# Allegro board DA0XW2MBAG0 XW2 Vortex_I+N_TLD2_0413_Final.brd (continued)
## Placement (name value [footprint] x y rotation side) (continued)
C3637  1u/25V_6  [C0603]  348.29 23.99 270 top
C3638  2.2U/10V_4  [C0402]  356.14 23.71 180 top
C3639  100p/50V_4  [C0402]  356.24 11.42 180 top
C3640  100p/50V_4  [C0402]  354.49 3.39 270 top
C3641  100p/50V_4  [C0402]  356.39 7.2 0 top
C3642  0.1u/16V_4  [C0402]  356.39 25.24 270 top
C3643  0.1u/16V_4  [C0402]  353.42 10.07 180 top
C3644  0.1u/16V_4  [C0402]  355.51 16.09 180 top
C3645  0.1U/16V_2  [C0201]  196.53 158.54 180 top
C3646  0.1U/16V_2  [C0201]  223.04 157.32 270 top
C3647  10u/6.3V_6  [C0603]  195.87 158.55 0 bottom
C3648  0.1u/16V_4  [C0402]  195.87 156.27 180 bottom
C3649  0.1u/16V_4  [C0402]  195.87 157.28 180 bottom
C3650  10u/6.3V_6  [C0603]  227.62 153.23 90 bottom
C3651  0.1u/16V_4  [C0402]  225.84 156.94 270 top
C3652  0.1u/16V_4  [C0402]  226.84 156.95 270 top
C3653  10u/25V_6  [C0603]  203.74 154.11 180 bottom
C3654  10u/25V_6  [C0603]  203.74 155.63 180 bottom
C3655  10u/25V_6  [C0603]  203.74 157.16 180 bottom
C3656  10u/25V_6  [C0603]  203.74 158.68 180 bottom
C3657  10u/25V_6  [C0603]  223.04 153.22 90 bottom
C3658  10u/25V_6  [C0603]  224.57 153.22 90 bottom
C3659  10u/25V_6  [C0603]  226.09 153.22 90 bottom
C3660  10u/25V_6  [C0603]  221.52 153.22 90 bottom
C3661  47p/50V_4  [C0402]  214.54 153.47 90 top
C3662  47p/50V_4  [C0402]  213.52 153.47 90 top
C3663  47p/50V_4  [C0402]  212.5 153.47 90 top
C3664  47p/50V_4  [C0402]  211.49 153.47 90 top
C3665  47p/50V_4  [C0402]  206.03 156.55 270 top
C3666  47p/50V_4  [C0402]  218.09 155.41 90 top
C3667  47p/50V_4  [C0402]  218.09 152.62 90 top
C3668  47p/50V_4  [C0402]  205.77 153.63 90 top
C3669  *10u/25V_6  [C0603]  330.87 10.92 270 top
C3670  *10u/25V_6  [C0603]  329.44 10.92 270 top
C4000  0.1U/16V_4  [C0402]  28.1 118.07 270 bottom
C4001  0.1U/16V_4  [C0402]  27.08 118.07 270 bottom
C4002  22U/6.3V_6  [C0603]  31.02 125.95 270 bottom
C4003  0.1U/16V_4  [C0402]  23.27 124.04 180 top
C4004  1U/10V_4  [C0402]  26.07 126.96 90 top
C4005  0.1U/16V_4  [C0402]  23.15 126.07 180 top
C4006  10u/6.3V_6  [C0603]  24.8 126.96 270 top
C4007  10u/6.3V_6  [C0603]  23.78 117.31 270 bottom
C4008  10P/50V_4  [C0402]  19.08 128.23 180 bottom
C4009  12p/50V_4  [C0402]  20.86 128.23 0 bottom
C4010  1U/6.3V_4  [C0402]  26.96 138.39 0 bottom
C4011  0.01U/100V_6  [C0603]  23.15 137.25 180 bottom
C4012  0.1U/16V_4  [C0402]  26.96 142.46 0 bottom
C4013  0.01U/100V_6  [C0603]  23.15 138.77 180 bottom
C4014  0.1U/16V_4  [C0402]  26.96 143.47 0 bottom
C4015  0.01U/100V_6  [C0603]  23.15 143.73 180 bottom
C4016  0.1U/16V_4  [C0402]  26.96 144.49 0 bottom
C4017  0.01U/100V_6  [C0603]  23.15 145.25 180 bottom
C4018  0.1U/16V_4  [C0402]  26.96 137.38 0 bottom
C4019  10P/3KV_1808  [CC1808]  24.54 134.96 180 bottom
C4100  1u/6.3V_4  [C0402]  326.04 74.64 90 bottom
C4101  0.1u/16V_4  [C0402]  329.85 79.59 270 bottom
C4102  0.1u/16V_4  [C0402]  328.84 79.59 270 bottom
C4103  4.7u/6.3V_4  [C0402_2]  331.63 79.72 0 bottom
C4104  0.1u/16V_4  [C0402]  333.66 78.45 270 bottom
C4105  3.3P/50V_4  [C0402]  335.69 78.45 90 bottom
C4106  10u/6.3V/X5R_4  [C0402]  334.68 78.45 90 bottom
C4107  10u/6.3V/X5R_4  [C0402]  334.75 59.86 180 bottom
C4108  0.01U/50V_4  [C0402]  336.71 77.05 90 bottom
C4109  0.1u/16V_4  [C0402]  333.03 61.3 90 bottom
C4110  0.01U/50V_4  [C0402]  334.02 61.3 270 bottom
C4111  *0_4/S  [S0402]  350.3 69.31 0 bottom
C4112  *0_4/S  [S0402]  350.3 68.29 0 bottom
C4200  470p/50V_4  [C0402]  304.32 12.92 90 top
C4201  3.3P/50V_4  [C0402]  331.78 21.46 0 bottom
C4202  10U/6.3V_4  [C0402]  331.78 19.3 180 bottom
C4203  *0.1u/16V_4  [C0402]  341.03 19.3 90 bottom
C4204  4.7u/6.3V_4  [C0402_2]  311.63 10.09 180 top
C4205  1u/6.3V_4  [C0402]  344.05 21.91 180 bottom
C4206  56p/50V_4  [C0402]  342.89 28.15 270 top
C4207  18p/50V_4  [C0402]  307.37 12.92 90 top
C4208  56p/50V_4  [C0402]  341.87 28.16 270 top
C4209  0.1u/16V_4  [C0402]  346.77 19.06 0 bottom
C4210  18p/50V_4  [C0402]  309.66 12.92 90 top
C4211  18p/50V_4  [C0402]  311.63 11.23 0 top
C4212  220u/6.3V_3528H1.9  [C3528]  340.01 25.54 0 top
C4213  68P/50V_4  [C0402]  346.77 18.06 180 bottom
C4214  18p/50V_4  [C0402]  308.39 12.92 90 top
C4215  33p/50V_4  [C0402]  345.68 5.94 90 bottom
C4216  0.1u/16V_4  [C0402]  311.63 12.25 180 top
C4217  10U/6.3V_4  [C0402]  349.74 18.07 0 bottom
C4218  56p/50V_4  [C0402]  344.99 20.54 90 bottom
C4219  *220u/6.3V_3528H1.9  [C3528]  330.69 26.3 270 top
C4220  *6.8P/50V_4  [C0402]  331.78 20.44 180 bottom
C4221  33p/50V_4  [C0402]  328.58 20.82 0 bottom
C4222  47p/50V_4  [C0402]  328.58 19.81 0 bottom
C4223  56p/50V_4  [C0402]  328.58 18.79 180 bottom
C4224  68P/50V_4  [C0402]  328.58 17.78 180 bottom
C4225  *22u/6.3V_6  [C0603]  329.85 18.12 180 top
C4226  *47u/6.3V_8  [C0805]  329.98 16.35 180 top
C5001  0.1u/16V_4  [C0402]  39.78 47.21 90 bottom
C5002  10u/6.3V_6  [C0603]  41.18 47.21 90 bottom
C5003  10U/10V/X5R_8  [C0805]  42.96 47.46 270 bottom
C5100  68p/50V_4  [C0402]  318.29 12.28 0 top
C5101  0.1u/16V_4  [C0402]  318.75 5.17 0 top
C5102  1000P/50V_4  [C0402]  318.29 9.23 0 top
C5103  3.3p/50V_4  [C0402]  309.02 26 180 bottom
C5104  1000P/50V_4  [C0402]  318.29 10.25 0 top
C5105  3.3p/50V_4  [C0402]  318.29 11.27 0 top
C5106  1000P/50V_4  [C0402]  309.02 28.03 180 bottom
C5107  0.1u/16V_4  [C0402]  313.09 31.97 90 bottom
C5112  0.1u/16V_4  [C0402]  309.02 27.01 180 bottom
C5113  1000P/50V_4  [C0402]  312.73 44.69 90 bottom
C5114  68p/50V_4  [C0402]  309.02 24.98 180 bottom
C5115  0.1u/16V_4  [C0402]  311.31 19.9 180 bottom
C5121  *22u/6.3V_6  [C0603]  308.98 34.18 0 bottom
C5122  *47u/6.3V_8  [C0805]  309.22 32.44 0 bottom
C6001  10U/6.3V_4  [C0402]  276 28.03 180 top
C6002  0.1u/6.3V_2  [C0201]  274.73 27.9 90 top
C6003  10U/6.3V_4  [C0402]  260.08 28.67 270 bottom
C6004  1U/10V_2  [C0201]  266.54 33.57 270 top
C6006  0.1u/6.3V_2  [C0201]  262.29 27.6 180 bottom
C6007  1U/10V_2  [C0201]  268.38 20.66 90 bottom
C6008  2200P/50V_4  [C0402]  262.13 26.25 270 bottom
C6009  2200P/50V_4  [C0402]  261.17 26.25 270 bottom
C6011  2200P/50V_4  [C0402]  260.2 26.25 90 bottom
C6012  10U/6.3V_4  [C0402]  270.03 34.76 0 bottom
C6015  0.1u/6.3V_2  [C0201]  264.32 24.35 180 top
C6016  0.1u/6.3V_2  [C0201]  270.03 33.75 0 bottom
C6017  4.7u/6.3V_4  [C0402]  260.64 25.24 270 top
C6018  0.1u/6.3V_2  [C0201]  261.53 25.62 270 top
C6019  1U/10V_2  [C0201]  261.65 26.76 0 top
C6020  VARISTOR  [C0402]  35.47 141.7 90 bottom
C6022  VARISTOR  [C0402]  30.89 141.57 0 bottom
C6029  0.1u/16V_4  [C0402]  263.81 13.17 0 top
C6030  0.1u/6.3V_2  [C0201]  269.15 22.44 270 top
C6031  0.1u/6.3V_2  [C0201]  274.35 25.74 90 top
C6032  0.1u/6.3V_2  [C0201]  266.86 34.13 270 bottom
C6033  *0.1u/6.3V_2  [C0201]  251.11 50.38 270 top
C6038  2200P/50V_4  [C0402]  258.78 22.62 180 top
C6039  2200P/50V_4  [C0402]  258.86 24.6 270 top
C6201  0.1u/16V_4  [C0402]  316.26 49.75 90 bottom
C6202  0.1u/16V_4  [C0402]  299.75 59.27 270 bottom
C6203  1u/10V_4  [C0402]  302.22 57.19 270 bottom
C6204  *0.1u/16V_4  [C0402]  298.74 59.27 270 bottom
C6300  *10p/50V_4  [C0402]  336.68 87.9 270 bottom
C6301  *VARISTOR  [C0402]  26.83 94.71 90 bottom
C6302  10u/6.3V_6  [C0603]  25.31 97.12 90 bottom
C6303  *10p/50V_4  [C0402]  25.81 94.71 270 bottom
C6304  0.1u/16V_4  [C0402]  26.58 97.12 270 bottom
C6305  47p/50V_4  [C0402]  25.18 100.04 0 bottom
C6306  10u/6.3V_6  [C0603]  319.69 72.35 0 bottom
C6307  0.1u/16V_4  [C0402]  319.69 73.62 180 bottom
C6308  *VARISTOR  [C0402]  335.69 87.9 90 bottom
C6309  47p/50V_4  [C0402]  323.37 72.73 180 bottom
C6351  *10p/50V_4  [C0402]  101.63 3.34 90 top
C6352  12p/50V_4  [C0402]  104.93 3.34 90 top
C6353  0.1u/16V_4  [C0402]  105.44 5.93 90 top
C6354  12p/50V_4  [C0402]  102.9 3.34 90 top
C6355  *10p/50V_4  [C0402]  100.62 3.34 90 top
C6401  0.01U/50V_4  [C0402]  170.09 88.18 0 bottom
C6402  2200P/50V_4  [C0402]  188.75 47.59 90 top
C6403  0.1u/16V_4  [C0402]  121.44 112.2 0 top
C6500  0.1u/16V_4  [C0402]  294.29 56.73 90 top
C6501  0.1u/16V_4  [C0402]  299.37 56.61 90 top
C6502  0.1u/16V_4  [C0402]  307.5 45.61 270 bottom
C6503  0.1u/16V_4  [C0402]  305.09 41.49 270 bottom
C6504  1u/6.3V_4  [C0402]  291.75 50.38 270 top
C6800  0.1u/16V_4  [C0402]  238.03 50.89 180 bottom
C6801  *VARISTOR  [C0402]  233.97 41.87 0 bottom
C6802  *VARISTOR  [C0402]  232.57 36.74 270 bottom
C6803  *VARISTOR  [C0402]  230.92 42.89 180 bottom
C6804  *VARISTOR  [C0402]  230.92 46.95 180 bottom
C6805  *VARISTOR  [C0402]  233.97 42.89 0 bottom
C6806  *VARISTOR  [C0402]  233.97 38.83 0 bottom
C6807  *VARISTOR  [C0402]  233.97 43.91 0 bottom
C6808  *VARISTOR  [C0402]  230.92 43.91 180 bottom
C6809  *VARISTOR  [C0402]  230.92 41.87 180 bottom
C6810  *VARISTOR  [C0402]  230.92 44.92 180 bottom
C6811  *VARISTOR  [C0402]  233.97 47.97 0 bottom
C6812  *VARISTOR  [C0402]  231.55 36.74 270 bottom
C6813  *VARISTOR  [C0402]  230.92 47.97 180 bottom
C6814  *VARISTOR  [C0402]  230.92 45.94 180 bottom
C6815  *VARISTOR  [C0402]  233.97 48.99 0 bottom
C6816  *VARISTOR  [C0402]  233.97 45.94 0 bottom
C6817  *VARISTOR  [C0402]  230.92 39.84 180 bottom
C6818  *VARISTOR  [C0402]  233.97 44.92 0 bottom
C6819  *VARISTOR  [C0402]  230.92 50 180 bottom
C6820  *VARISTOR  [C0402]  233.97 51.02 0 bottom
C6821  *VARISTOR  [C0402]  230.92 40.86 180 bottom
C6822  *VARISTOR  [C0402]  233.97 46.95 0 bottom
C6823  *VARISTOR  [C0402]  233.97 50 0 bottom
C6824  *VARISTOR  [C0402]  233.97 37.81 0 bottom
C6825  1u/10V_4  [C0402]  196.12 45.94 0 top
C6826  *VARISTOR  [C0402]  233.97 40.86 0 bottom
C6827  *VARISTOR  [C0402]  230.92 48.99 180 bottom
C6828  *VARISTOR  [C0402]  233.97 39.84 0 bottom
C6829  *VARISTOR  [C0402]  244.89 53.68 180 top
C6830  *VARISTOR  [C0402]  231.05 51.02 180 bottom
C6831  *VARISTOR  [C0402]  233.97 52.03 0 bottom
C7000  470p/50V_4  [C0402]  349.79 78.45 270 top
C7001  0.1u/16V_4  [C0402]  18.27 105.73 270 top
C7002  470p/50V_4  [C0402]  19.29 105.73 270 top
C7003  0.1u/16V_4  [C0402]  16.95 95.11 270 top
C7004  470p/50V_4  [C0402]  15.93 95.11 270 top
C7005  1000P/50V_4  [C0402]  17.25 105.73 90 top
C7006  1000P/50V_4  [C0402]  17.96 95.11 90 top
C7007  0.1u/16V_4  [C0402]  354.62 78.45 90 top
C7008  470p/50V_4  [C0402]  350.81 78.45 90 top
C7009  1000P/50V_4  [C0402]  352.61 78.45 270 top
C7010  PESD5V0X2UM  [DFN1006H4-3-1X0_6-3P]  16.16 108.8 270 top
C7011  PESD5V0X2UM  [DFN1006H4-3-1X0_6-3P]  15.91 87.34 270 top
C7012  PESD5V0X2UM  [DFN1006H4-3-1X0_6-3P]  355.38 77.05 90 bottom
C7013  4.7u/6.3V_4  [C0402_2]  353.22 88.74 0 top
C7014  4.7u/6.3V_4  [C0402_2]  17.89 96.76 180 top
C7015  4.7u/6.3V_4  [C0402_2]  22.18 96.05 0 top
C7016  0.1u/16V_4  [C0402]  353.22 86.7 0 top
C7017  0.1u/16V_4  [C0402]  17.89 97.91 180 top
C7018  0.1u/16V_4  [C0402]  22.18 94.91 0 top
C7019  100u/6.3V_3528H1.9  [C3528]  349.79 83.02 270 top
C7020  470p/50V_4  [C0402]  18.96 95.11 90 top
C7021  100u/6.3V_3528H1.9  [C3528]  16.24 101.54 90 top
C7022  470p/50V_4  [C0402]  20.35 101.94 270 top
C7023  100u/6.3V_3528H1.9  [C3528]  16.92 90.85 0 top
C7100  0.47U/25V_4  [C0402]  361.6 113.76 270 bottom
C7102  0.47U/25V_4  [C0402]  363.66 133.85 90 bottom
C7103  10u/25V_8  [C0805]  364.47 129.88 270 bottom
C7104  0.47U/25V_4  [C0402]  361.8 132.81 270 bottom
C7105  0.47U/25V_4  [C0402]  361.6 130.39 270 bottom
C7107  10u/25V_8  [C0805]  364.47 113.25 270 bottom
C7108  0.47U/25V_4  [C0402]  363.84 117.16 90 bottom
C7109  0.47U/25V_4  [C0402]  361.83 116.12 270 bottom
C7110  0.47U/25V_4  [C0402]  364.65 134.71 90 bottom
C7111  0.47U/25V_4  [C0402]  364.8 118.12 90 bottom
C7138  47u/10V_8  [C0805]  352.71 137.63 180 top
C7139  *47u/10V_8  [C0805]  351.95 135.6 180 top
C7140  10U/6.3V_4  [C0402]  348.77 139.16 270 top
C7141  0.1u/16V_4  [C0402]  349.76 139.16 270 top
C7146  10U/6.3V_4  [C0402]  350.68 134.08 180 top
C7147  0.1u/16V_4  [C0402]  350.68 133.11 180 top
C7152  0.001u/50V_4  [C0402]  354.46 143.27 0 top
C7153  0.001u/50V_4  [C0402]  342.55 132.3 180 top
C7154  *47u/10V_8  [C0805]  348.14 137.17 0 top
C7155  47u/10V_8  [C0805]  348.14 135.19 0 top
C7200  0.1u/16V_4  [C0402]  289.21 10.25 0 top
C7201  4.7u/6.3V_4  [C0402_2]  289.21 9.11 0 top
C7300  0.1U/16V_4  [C0402]  286.29 14.31 0 top
C7301  1U/10V_4  [C0402]  283.14 8.93 90 top
C7302  82P/50V_4  [C0402]  284.21 8.93 90 top
C7303  1U/10V_4  [C0402]  284.26 20.77 270 bottom
C7304  0.1U/16V_4  [C0402]  282.2 14.37 270 top
C7305  1U/10V_4  [C0402]  282.07 8.93 90 top
C7306  0.1U/16V_4  [C0402]  281.85 20.77 270 bottom
C7307  1U/10V_4  [C0402]  279.66 11.52 90 top
C7308  0.1U/16V_4  [C0402]  280.7 11.52 90 top
C7309  0.1U/16V_4  [C0402]  280.83 20.77 270 bottom
C7310  1U/10V_4  [C0402]  279.81 20.77 270 bottom
C7311  *47P/50V_4  [C0402]  277.53 9.11 270 top
C7312  1U/10V_4  [C0402]  280.17 14.37 270 top
C7313  0.1U/16V_4  [C0402]  279.15 14.37 270 top
C7314  *12pF_4  [C0402]  288.96 20.36 180 bottom
C7315  *12pF_4  [C0402]  287.05 20.36 0 bottom
C7316  0.1u/16V_4  [C0402]  28.71 75.17 270 bottom
C7317  10U/6.3VS_6  [C0603]  27.46 75.27 90 bottom
C7318  1u/10V_4  [C0402]  25.56 74.39 270 bottom
C7319  0.1u/16V_4  [C0402]  34.27 67.2 0 bottom
C7320  1u/10V_4  [C0402]  24.52 67.58 0 bottom
C7321  0.1u/16V_4  [C0402]  34.27 68.21 0 bottom
C7322  *100p/50V_4  [C0402]  33.51 66.18 0 bottom
C7323  0.1u/16V_4  [C0402]  27.69 64.4 90 bottom
C7324  0.1u/16V_4  [C0402]  32.09 65.29 270 bottom
C7325  4.7U/6.3VS_4  [C0402]  26.68 64.4 270 bottom
C7326  10u/6.3V_6  [C0603]  31.12 63.64 0 bottom
C7327  0.1u/16V_4  [C0402]  30.69 64.91 180 bottom
C7328  0.1u/16V_4  [C0402]  36.23 63.08 270 top
C7329  4.7U/6.3V_6  [C0603]  36.35 60.8 270 top
C7330  0.1u/16V_4  [C0402]  34.58 63.79 270 bottom
C7331  *0.1u/16V_4  [C0402]  38.54 65.04 180 bottom
C7332  4.7U/6.3V_6  [C0603]  36.61 67.02 90 bottom
C8000  0.22uF/6.3V_2  [C0201]  337.22 107.53 180 bottom
C8001  0.22uF/6.3V_2  [C0201]  337.22 108.29 180 bottom
C8002  0.22uF/6.3V_2  [C0201]  337.22 110.58 180 bottom
C8003  0.22uF/6.3V_2  [C0201]  337.22 111.34 180 bottom
C8004  0.22uF/6.3V_2  [C0201]  337.22 114.39 180 bottom
C8005  0.22uF/6.3V_2  [C0201]  337.22 113.63 180 bottom
C8006  0.22uF/6.3V_2  [C0201]  337.22 117.44 180 bottom
C8007  0.22uF/6.3V_2  [C0201]  337.22 116.68 180 bottom
C8008  0.22uF/6.3V_2  [C0201]  348.52 105.37 90 bottom
C8009  0.22uF/25V_2  [C0201]  341.41 124.04 270 bottom
C8010  0.22uF/6.3V_2  [C0201]  346.49 105.37 90 bottom
C8011  0.33UF/25V_4  [C0402]  343.08 124.3 90 bottom
C8012  0.33UF/25V_4  [C0402]  342.53 124.27 90 top
C8013  0.33UF/25V_4  [C0402]  343.49 124.27 90 top
C8014  0.22uF/6.3V_2  [C0201]  349.28 105.37 90 bottom
C8015  0.22uF/25V_2  [C0201]  342.17 124.04 270 bottom
C8016  0.22uF/6.3V_2  [C0201]  347.25 105.37 90 bottom
C8017  0.33UF/25V_4  [C0402]  344.08 124.3 90 bottom
C8018  0.22uF/6.3V_2  [C0201]  344.46 105.37 90 bottom
C8019  0.22uF/6.3V_2  [C0201]  345.22 105.37 90 bottom
C8020  0.22uF/25V_2  [C0201]  345.07 125.06 270 top
C8021  0.22uF/6.3V_2  [C0201]  343.19 105.37 90 bottom
C8022  0.22uF/25V_2  [C0201]  344.35 125.06 270 top
C8023  0.22uF/6.3V_2  [C0201]  342.42 105.37 90 bottom
C8024  *0_2/S  [S0201]  351.82 116.3 180 top
C8025  0.22uF/6.3V_2  [C0201]  354.36 111.34 180 bottom
C8026  *0_2/S  [S0201]  351.82 115.53 180 top
C8027  0.22uF/6.3V_2  [C0201]  354.36 110.58 180 bottom
C8028  0.22uF/6.3V_2  [C0201]  348.9 122.62 270 bottom
C8029  0.22uF/6.3V_2  [C0201]  348.16 122.62 270 bottom
C8030  0.22uF/6.3V_2  [C0201]  349.03 122.65 270 top
C8031  0.22uF/6.3V_2  [C0201]  349.79 122.65 270 top
C8032  0.33UF/25V_4  [C0402]  345.9 124.7 90 top
C8033  0.22uF/6.3V_2  [C0201]  350.43 122.9 270 bottom
C8034  0.33UF/25V_4  [C0402]  346.87 124.7 90 top
C8035  0.22uF/6.3V_2  [C0201]  351.19 122.9 270 bottom
C8036  0.22uF/25V_2  [C0201]  344.96 124.07 270 bottom
C8037  0.22uF/6.3V_2  [C0201]  351.95 122.9 270 bottom
C8038  0.22uF/25V_2  [C0201]  345.73 124.07 270 bottom
C8039  0.22uF/6.3V_2  [C0201]  352.71 122.9 270 bottom
C8040  0.22uF/6.3V_2  [C0201]  356.01 110.07 180 bottom
C8041  0.33UF/25V_4  [C0402]  347.55 124.02 90 bottom
C8042  0.22uF/6.3V_2  [C0201]  356.01 109.18 180 bottom
C8043  0.33UF/25V_4  [C0402]  346.59 124.02 90 bottom
C8044  0.22uF/25V_2  [C0201]  348.22 124.4 180 top
C8045  0.22uF/25V_2  [C0201]  348.22 125.14 180 top
C8046  *0_2/S  [S0201]  351.82 114.8 180 top
C8047  *0_2/S  [S0201]  351.82 114.06 180 top
C8050  8.2p/50V_4  [C0402]  338.28 120.61 0 bottom
C8051  12p/50V_4  [C0402]  336.56 120.61 180 bottom
C8052  0.1u/16V_4  [C0402]  314.61 67.78 90 bottom
C8053  10U/6.3V_4  [C0402]  345.6 115.91 180 top
C8054  1u/6.3V_4  [C0402]  345.19 117.44 90 top
C8055  1u/6.3V_4  [C0402]  346.21 117.44 90 top
C8056  1u/6.3V_4  [C0402]  350.04 117.57 90 top
C8057  1u/6.3V_4  [C0402]  351.06 117.57 90 top
C8058  10U/6.3V_4  [C0402]  347.38 117.36 90 top
C8059  10U/6.3V_4  [C0402]  348.9 117.46 90 top
C8060  10U/6.3V_4  [C0402]  351.7 119.34 90 top
C8061  10U/6.3V_4  [C0402]  350.17 119.22 180 top
C8062  10U/6.3V_4  [C0402]  347.4 114.6 270 top
C8063  1u/6.3V_4  [C0402]  347.12 111.98 180 top
C8064  1u/6.3V_4  [C0402]  345.55 111.67 270 top
C8065  1u/6.3V_4  [C0402]  344.25 111.67 270 top
C8066  1u/6.3V_4  [C0402]  344.2 113.5 270 top
C8067  1u/6.3V_4  [C0402]  344.2 115.28 270 top
C8068  1u/6.3V_4  [C0402]  342.93 111.72 270 top
C8069  1u/6.3V_4  [C0402]  346.11 119.09 180 top
C8070  1u/6.3V_4  [C0402]  347.89 119.09 0 top
C8071  1u/6.3V_4  [C0402]  343.82 118.2 0 top
C8072  1u/6.3V_4  [C0402]  343.82 117.18 0 top
C8073  10U/6.3V_4  [C0402]  340.01 109.82 270 top
C8074  1u/6.3V_4  [C0402]  340.04 114.49 180 top
C8075  1u/6.3V_4  [C0402]  340.04 113.5 180 top
C8076  1u/6.3V_4  [C0402]  340.04 112.54 180 top
C8077  1u/6.3V_4  [C0402]  340.01 111.44 180 top
C8078  1u/6.3V_4  [C0402]  340.77 119.19 0 top
C8079  1U/6.3V_2  [C0201]  347.96 113.25 270 top
C8080  47U/6.3V_8  [C0805]  355.12 123.03 180 bottom
C8081  47U/6.3V_8  [C0805]  355.12 120.99 180 bottom
C8082  47U/6.3V_8  [C0805]  355.12 118.71 180 bottom
C8083  1u/6.3V_4  [C0402]  353.47 125.31 90 bottom
C8084  1u/6.3V_4  [C0402]  352.46 125.31 90 bottom
C8085  1u/6.3V_4  [C0402]  354.49 125.31 90 bottom
C8086  1u/6.3V_4  [C0402]  355.51 125.31 90 bottom
C8087  1u/6.3V_4  [C0402]  346.21 114.26 270 top
C8088  1u/6.3V_4  [C0402]  342.3 118.76 90 top
C8089  1u/6.3V_4  [C0402]  341.38 115.53 90 top
C8090  1u/6.3V_4  [C0402]  343.82 119.22 0 top
C8091  1u/6.3V_4  [C0402]  347.12 110.96 180 top
C8502  1u/25V_4  [C0402]  341.92 97.25 0 top
C8506  1u/25V_4  [C0402]  337.8 100.52 90 bottom
C8507  390p/50V_4  [C0402]  347.25 89.37 270 bottom
C8508  390p/50V_4  [C0402]  338.11 91.4 180 bottom
C8511  390p/50V_4  [C0402]  338.11 92.42 180 bottom
C8512  390p/50V_4  [C0402]  343.44 94.32 180 top
C8513  0.1u/25V_4  [C0402]  342.81 92.67 180 top
C8580  1u/25V_4  [C0402]  344.46 100.55 90 bottom
C8586  0.1u/25V_4  [C0402]  339 88.48 0 bottom
C8587  10U/6.3V_4  [C0402]  339 89.5 180 bottom
C8613  0.1u/25V_4  [C0402]  341.92 98.26 180 top
C9000  0.1u/16V_4  [C0402]  165.89 94.71 0 top
C9001  *0.1u/16V_4  [C0402]  143.03 27.27 90 bottom
C9002  *0.1u/16V_4  [C0402]  129.83 116.93 0 top
C9003  47p/50V_4  [C0402]  185.71 126.2 90 bottom
C9004  0.22u/6.3V_2  [C0201]  184.1 104.83 180 bottom
C9005  0.22u/6.3V_2  [C0201]  184.1 105.6 180 bottom
C9006  0.22u/6.3V_2  [C0201]  185.63 106.61 180 bottom
C9007  0.22u/6.3V_2  [C0201]  185.63 105.85 180 bottom
C9008  0.22u/6.3V_2  [C0201]  184.1 106.87 180 bottom
C9009  0.22u/6.3V_2  [C0201]  184.1 107.63 180 bottom
C9010  0.22u/6.3V_2  [C0201]  185.63 108.64 180 bottom
C9011  0.22u/6.3V_2  [C0201]  185.63 107.88 180 bottom
C9012  0.22u/6.3V_2  [C0201]  184.1 108.9 180 bottom
C9013  0.22u/6.3V_2  [C0201]  184.1 109.66 180 bottom
C9014  0.22u/6.3V_2  [C0201]  185.63 110.68 180 bottom
C9015  0.22u/6.3V_2  [C0201]  185.63 109.92 180 bottom
C9016  0.22u/6.3V_2  [C0201]  184.1 110.94 180 bottom
C9017  0.22u/6.3V_2  [C0201]  184.1 111.69 180 bottom
C9018  0.22u/6.3V_2  [C0201]  185.63 111.95 180 bottom
C9019  0.22u/6.3V_2  [C0201]  185.63 112.71 180 bottom
C9020  0.22u/6.3V_2  [C0201]  184.1 112.96 180 bottom
C9021  0.22u/6.3V_2  [C0201]  184.1 113.72 180 bottom
C9022  0.22u/6.3V_2  [C0201]  185.63 114.74 180 bottom
C9023  0.22u/6.3V_2  [C0201]  185.63 113.98 180 bottom
C9024  0.22u/6.3V_2  [C0201]  184.1 114.99 180 bottom
C9025  0.22u/6.3V_2  [C0201]  184.1 115.76 180 bottom
C9026  0.22u/6.3V_2  [C0201]  185.63 116.77 180 bottom
C9027  0.22u/6.3V_2  [C0201]  185.63 116.01 180 bottom
C9028  0.22u/6.3V_2  [C0201]  184.1 117.03 180 bottom
C9029  0.22u/6.3V_2  [C0201]  184.1 117.79 180 bottom
C9030  0.22u/6.3V_2  [C0201]  185.63 118.8 180 bottom
C9031  0.22u/6.3V_2  [C0201]  185.63 118.04 180 bottom
C9032  0.22u/6.3V_2  [C0201]  184.1 119.06 180 bottom
C9033  0.22u/6.3V_2  [C0201]  184.1 119.82 180 bottom
C9034  0.22u/6.3V_2  [C0201]  185.63 120.81 180 bottom
C9035  0.22u/6.3V_2  [C0201]  185.63 120.07 180 bottom
C9036  22u/6.3V_6  [C0603]  154.59 117.06 180 top
C9037  47u/6.3V_8  [C0805]  147.73 115.79 180 top
C9038  10u/6.3V_4  [C0402_2]  149.77 118.33 0 top
C9039  10u/6.3V_4  [C0402_2]  149.77 119.55 0 top
C9040  10u/6.3V_4  [C0402_2]  153.32 119.6 0 top
C9041  10u/6.3V_4  [C0402_2]  155.1 119.6 180 top
C9042  10u/6.3V_4  [C0402_2]  151.54 118.33 180 top
C9043  22u/6.3V_6  [C0603]  150.68 116.98 0 top
C9044  22u/6.3V_6  [C0603]  150.91 115.53 0 top
C9045  22u/6.3V_6  [C0603]  147.48 120.44 180 top
C9046  22u/6.3V_6  [C0603]  147.48 119.01 180 top
C9047  22u/6.3V_6  [C0603]  154.59 115.53 180 top
C9048  22u/6.3V_6  [C0603]  147.48 117.57 180 top
C9049  47u/6.3V_8  [C0805]  147.71 111.75 180 top
C9050  47u/6.3V_8  [C0805]  147.71 113.78 180 top
C9051  10u/6.3V_4  [C0402_2]  151.54 119.57 180 top
C9052  10u/6.3V_4  [C0402_2]  155.1 118.38 180 top
C9053  10u/6.3V_4  [C0402_2]  147.58 121.76 180 top
C9054  10u/6.3V_4  [C0402_2]  130.11 126.91 0 top
C9055  10u/6.3V_4  [C0402_2]  153.32 118.38 0 top
C9056  1u/10V_2  [C0201]  149.64 121.22 180 top
C9057  1u/10V_2  [C0201]  153.07 122.65 180 top
C9058  1u/10V_2  [C0201]  151.29 122.61 0 top
C9059  1u/10V_2  [C0201]  151.29 121.85 0 top
C9060  1u/10V_2  [C0201]  153.07 121.88 180 top
C9061  1u/10V_2  [C0201]  149.64 121.98 180 top
C9062  1u/10V_2  [C0201]  149.64 122.74 180 top
C9063  1u/10V_2  [C0201]  151.29 121.09 0 top
C9064  1u/10V_2  [C0201]  153.07 121.12 180 top
C9065  1u/10V_2  [C0201]  154.08 121.88 0 top
C9066  1u/10V_2  [C0201]  147.99 122.72 0 top
C9067  1u/10V_2  [C0201]  154.08 121.12 0 top
C9068  220u/2.5V_3528H1.1  [C3528]  170.16 111.24 0 top
C9069  22u/6.3V_6  [C0603]  171.23 115.43 0 top
C9070  22u/6.3V_6  [C0603]  171.23 113.81 0 top
C9072  22U/6.3V_6  [C0603]  162.97 91.91 0 top
C9073  22U/6.3V_6  [C0603]  157.89 91.78 0 top
C9074  22U/6.3V_6  [C0603]  157.89 93.28 0 top
C9075  22U/6.3V_6  [C0603]  162.97 93.4 0 top
C9076  10u/6.3V_4  [C0402_2]  177.58 122.39 180 top
C9077  10u/6.3V_4  [C0402_2]  173.9 110.55 180 top
C9078  10u/6.3V_4  [C0402_2]  171.36 121.14 0 top
C9079  10u/6.3V_4  [C0402_2]  171.13 119.62 0 top
C9080  10u/6.3V_4  [C0402_2]  171.13 117.39 0 top
C9081  10U/6.3V_4  [C0402]  157.51 95.56 0 top
C9082  10U/6.3V_4  [C0402]  153.58 108.5 270 top
C9083  10U/6.3V_4  [C0402]  158.81 108.64 180 top
C9084  10U/6.3V_4  [C0402]  166.91 108.68 0 top
C9085  10U/6.3V_4  [C0402]  165.89 95.72 0 top
C9086  10U/6.3V_4  [C0402]  174.4 120.49 90 top
C9087  10U/6.3V_4  [C0402]  171.13 118.51 0 top
C9088  10U/6.3V_4  [C0402]  157.51 94.55 0 top
C9089  10U/6.3V_4  [C0402]  162.59 95.69 0 top
C9090  10U/6.3V_4  [C0402]  162.59 94.67 0 top
C9091  10U/6.3V_4  [C0402]  174.15 109.06 180 top
C9092  10U/6.3V_4  [C0402]  168.69 108.64 180 top
C9093  10U/6.3V_4  [C0402]  162.08 108.68 0 top
C9094  10u/6.3V_4  [C0402_2]  174.78 117.03 180 top
C9095  10u/6.3V_4  [C0402_2]  174.45 113.72 90 top
C9096  10u/6.3V_4  [C0402_2]  174.45 115.5 270 top
C9097  1U/10V_2  [C0201]  183.67 127.09 90 bottom
C9098  1U/10V_2  [C0201]  174.53 119.18 180 top
C9099  1U/10V_2  [C0201]  146.72 109.95 90 top
C9100  *1U/6.3V_4  [C0402]  174.4 112 270 top
C9101  1U/10V_2  [C0201]  182.79 122.01 0 bottom
C9102  22u/6.3V_6  [C0603]  157.64 117.57 0 top
C9103  220u/2.5V_3528H1.1  [C3528]  164.65 111.24 0 top
C9104  47U/6.3V_8  [C0805]  167.55 113.98 180 top
C9107  47U/6.3V_8  [C0805]  163.99 113.98 0 top
C9108  1U/10V_2  [C0201]  162.25 121.88 180 top
C9109  1U/10V_2  [C0201]  167.04 121.12 180 top
C9110  1U/10V_2  [C0201]  159.08 121.88 180 top
C9111  1U/10V_2  [C0201]  155.9 121.88 0 top
C9112  1U/10V_2  [C0201]  155.73 121.12 0 top
C9113  1U/10V_2  [C0201]  168.31 122.01 90 top
C9114  1U/10V_2  [C0201]  170.97 122.14 0 top
C9115  1U/10V_2  [C0201]  169.32 120.36 180 top
C9116  1U/10V_2  [C0201]  169.32 121.85 180 top
C9117  22u/6.3V_6  [C0603]  160.69 114.52 180 top
C9118  22u/6.3V_6  [C0603]  157.64 116.04 0 top
C9119  22u/6.3V_6  [C0603]  157.69 114.52 0 top
C9120  22u/6.3V_6  [C0603]  166.66 119.6 180 top
C9121  22u/6.3V_6  [C0603]  163.99 119.6 0 top
C9122  22u/6.3V_6  [C0603]  163.99 118.07 0 top
C9123  22u/6.3V_6  [C0603]  166.66 118.07 180 top
C9124  1U/10V_2  [C0201]  169.32 121.09 180 top
C9125  1U/10V_2  [C0201]  168.31 121.1 0 top
C9126  1U/10V_2  [C0201]  160.69 121.88 0 top
C9127  1U/10V_2  [C0201]  159.08 121.12 180 top
C9128  1U/10V_2  [C0201]  157.43 121.85 180 top
C9129  1U/10V_2  [C0201]  157.51 121.12 180 top
C9130  1U/10V_2  [C0201]  167.04 121.88 180 top
C9131  1U/10V_2  [C0201]  160.6 122.64 0 top
C9132  1U/10V_2  [C0201]  167.04 122.65 180 top
C9133  22u/6.3V_6  [C0603]  166.66 116.55 180 top
C9134  22u/6.3V_6  [C0603]  163.99 116.55 0 top
C9135  22u/6.3V_6  [C0603]  160.69 117.57 180 top
C9136  22u/6.3V_6  [C0603]  160.69 116.04 180 top
C9137  10U/6.3V_4  [C0402]  157.64 112.2 0 top
C9138  10U/6.3V_4  [C0402]  159.67 119.82 0 top
C9139  10U/6.3V_4  [C0402]  157.64 113.22 0 top
C9140  10U/6.3V_4  [C0402]  158.02 110.71 270 top
C9141  1U/10V_2  [C0201]  164.54 122.64 0 top
C9142  1U/10V_2  [C0201]  169.32 122.61 180 top
C9143  1U/10V_2  [C0201]  162.25 122.64 180 top
C9144  1U/10V_2  [C0201]  157.43 122.61 180 top
C9145  1U/10V_2  [C0201]  155.9 122.64 0 top
C9146  1U/10V_2  [C0201]  159.08 122.64 180 top
C9147  10U/6.3V_4  [C0402]  159.67 118.8 0 top
C9148  10U/6.3V_4  [C0402]  145.83 139.92 270 top
C9149  10U/6.3V_4  [C0402]  165.64 121.25 0 top
C9150  10U/6.3V_4  [C0402]  163.86 121.25 0 top
C9151  10U/6.3V_4  [C0402]  162.08 120.99 180 top
C9152  10U/6.3V_4  [C0402]  155.35 110.23 0 top
C9153  10U/6.3V_4  [C0402]  161.45 118.84 180 top
C9154  10U/6.3V_4  [C0402]  157.89 119.82 0 top
C9155  10U/6.3V_4  [C0402]  157.89 118.8 0 top
C9156  10U/6.3V_4  [C0402]  168.94 116.26 180 top
C9157  10U/6.3V_4  [C0402]  153.45 139.92 270 top
C9158  10U/6.3V_4  [C0402]  168.94 118.3 180 top
C9159  10U/6.3V_4  [C0402]  148.75 139.92 270 top
C9160  10U/6.3V_4  [C0402]  161.45 119.85 180 top
C9161  10U/6.3V_4  [C0402]  157 110.71 270 top
C9162  10U/6.3V_4  [C0402]  168.94 119.34 180 top
C9163  10U/6.3V_4  [C0402]  168.94 117.28 180 top
C9166  0.1u/16V_4  [C0402]  34.45 72.81 90 bottom
C9167  0.1u/16V_4  [C0402]  33.43 72.81 90 bottom
C9170  0.1u/16V_4  [C0402]  335.68 18.53 90 bottom
C9171  0.1u/16V_4  [C0402]  336.67 18.53 90 bottom
C9174  0.22uF/6.3V_2  [C0201]  337.22 106.01 180 bottom
C9175  0.22uF/6.3V_2  [C0201]  337.22 106.77 180 bottom
C9178  0.22uF/6.3V_2  [C0201]  337.22 109.06 180 bottom
C9179  0.22uF/6.3V_2  [C0201]  337.22 109.82 180 bottom
C9182  0.22uF/6.3V_2  [C0201]  336.96 112.87 180 bottom
C9183  0.22uF/6.3V_2  [C0201]  336.96 112.1 180 bottom
C9184  0.22uF/6.3V_2  [C0201]  337.22 115.15 180 bottom
C9185  0.22uF/6.3V_2  [C0201]  337.22 115.91 180 bottom
C9186  *12p/50V_4  [C0402]  252.64 88.2 180 bottom
C9187  *0.1u/16V_4  [C0402]  273.84 65.05 135 bottom
C9188  1u/6.3V_4  [C0402]  307.25 14.7 180 top
C9189  1u/6.3V_4  [C0402]  311.84 14.44 180 top
C9190  1u/6.3V_4  [C0402]  306.97 16.55 270 top
C9191  0.22uF/6.3V_2  [C0201]  325.15 29.43 180 bottom
C9192  0.22uF/6.3V_2  [C0201]  325.15 30.19 180 bottom
C9193  0.22uF/6.3V_2  [C0201]  325.51 31.97 180 bottom
C9194  0.22uF/6.3V_2  [C0201]  325.51 32.73 180 bottom
C9195  1000P/50V_4  [C0402]  239.94 78.2 315 bottom
C9196  0.22uF/6.3V_2  [C0201]  326.22 34.97 0 bottom
C9197  0.22uF/6.3V_2  [C0201]  326.22 34.2 0 bottom
C9198  0.22uF/6.3V_2  [C0201]  326.37 15.58 180 bottom
C9199  0.22uF/6.3V_2  [C0201]  326.37 16.35 180 bottom
C9200  0.1u/16V_4  [C0402]  355 67.91 0 bottom
C9201  0.22uF/6.3V_2  [C0201]  326.3 12.54 180 bottom
C9202  0.1u/16V_4  [C0402]  355 66.89 0 bottom
C9203  0.22uF/6.3V_2  [C0201]  326.3 13.3 180 bottom
C9204  0.1u/16V_4  [C0402]  26.83 116.17 270 bottom
C9205  0.1u/16V_4  [C0402]  25.81 116.17 270 bottom
C9206  0.22uF/6.3V_2  [C0201]  325.96 37.53 0 bottom
C9207  0.22uF/6.3V_2  [C0201]  325.96 36.77 0 bottom
C9208  0.22uF/6.3V_2  [C0201]  326.27 7.33 0 bottom
C9209  0.22uF/6.3V_2  [C0201]  326.27 6.57 0 bottom
C9210  0.22uF/6.3V_2  [C0201]  326.3 10.25 0 bottom
C9211  0.22uF/6.3V_2  [C0201]  326.3 9.49 0 bottom
C9212  18p/50V_4  [C0402]  236.76 78.83 45 bottom
C9213  18p/50V_4  [C0402]  235.49 77.05 135 bottom
C9214  18p/50V_4  [C0402]  270.59 63.56 225 bottom
C9215  18p/50V_4  [C0402]  271.85 64.81 45 bottom
C9216  *0.1u/16V_4  [C0402]  266.61 77.05 45 bottom
C9217  0.1u/16V_4  [C0402]  261.78 75.78 225 top
C9219  1u/6.3V_4  [C0402]  251.11 66.13 45 top
C9220  1u/6.3V_4  [C0402]  254.34 67.38 225 top
C9221  0.1u/16V_4  [C0402]  272.19 68.54 45 bottom
C9222  1u/6.3V_4  [C0402]  271.43 69.18 225 bottom
C9223  1u/6.3V_4  [C0402]  251.49 62.19 225 top
C9224  1u/6.3V_4  [C0402]  233.45 71.28 225 bottom
C9225  4.7u/6.3V_4  [C0402]  251.42 74.26 0 top
C9226  22U/6.3V_6  [C0603]  256.95 50.64 135 bottom
C9227  22U/6.3V_6  [C0603]  255.94 49.62 135 bottom
C9228  0.1u/16V_4  [C0402]  254.67 79.72 90 top
C9230  1u/6.3V_4  [C0402]  232.18 70.01 225 bottom
C9231  1u/6.3V_4  [C0402]  246.54 68.23 135 top
C9232  4.7u/6.3V_4  [C0402]  252.53 82.59 225 top
C9233  0.1u/16V_4  [C0402]  273.08 67.34 315 bottom
C9234  1u/6.3V_4  [C0402]  273.79 68.06 315 bottom
C9235  1u/6.3V_4  [C0402]  253.27 79.59 0 top
C9237  0.1u/16V_4  [C0402]  254.92 69.75 225 top
C9238  0.1u/16V_4  [C0402]  254.16 70.51 225 top
C9245  22U/6.3V_6  [C0603]  248.83 62.7 225 top
C9246  22U/6.3V_6  [C0603]  236.25 67.27 270 top
C9248  0.1u/16V_4  [C0402]  269.6 66.51 90 top
C9249  0.1u/16V_4  [C0402]  200.21 21.35 180 top
C9250  *0.022u/25V_4  [C0402]  309.66 62.19 0 top
C9251  *0.022u/25V_4  [C0402]  264.95 20.54 90 top
C9255  1u/6.3V_4  [C0402]  171.86 140.3 180 top
C9256  1U/10V_2  [C0201]  174.53 108.04 270 top
C9257  220u/2.5V_3528H1.1  [C3528]  153.78 112.51 180 top
C9262  *47U/6.3V_8  [C0805]  160.43 112.74 180 top
C9263  *47U/6.3V_8  [C0805]  160.43 110.71 180 top
C9264  *10u/6.3V_4  [C0402]  162.21 140.04 270 top
C9265  *10u/6.3V_4  [C0402]  166.91 140.04 270 top
C9266  *10u/6.3V_4  [C0402]  155.48 133.57 180 top
C9267  *10u/6.3V_4  [C0402]  164.62 140.04 270 top
C9268  *10u/6.3V_4  [C0402]  163.35 140.04 270 top
C9269  *10u/6.3V_4  [C0402]  157.13 139.92 270 top
C9270  *10u/6.3V_4  [C0402]  144.94 131.66 0 top
C9271  *10u/6.3V_4  [C0402]  144.81 133.44 0 top
C9272  *10u/6.3V_4  [C0402]  161.83 133.19 180 top
C9273  *10u/6.3V_4  [C0402]  155.73 139.92 270 top
C9274  *10u/6.3V_4  [C0402]  147.35 140.04 270 top
C9275  *10u/6.3V_4  [C0402]  165.64 140.04 270 top
C9276  *10u/6.3V_4  [C0402]  155.48 132.55 180 top
C9277  *10u/6.3V_4  [C0402]  144.81 139.92 270 top
C9278  *10u/6.3V_4  [C0402]  149.13 131.66 0 top
C9279  *10u/6.3V_4  [C0402]  144.81 134.58 0 top
C9280  *10u/6.3V_4  [C0402]  161.83 134.46 180 top
C9281  *10u/6.3V_4  [C0402]  153.58 131.66 180 top
C9282  *10u/6.3V_4  [C0402]  138.84 139.92 270 top
C9283  *10u/6.3V_4  [C0402]  139.86 139.92 270 top
C9284  *10u/6.3V_4  [C0402]  142.78 139.92 270 top
C9285  *1U/10V_2  [C0201]  156.62 120.74 90 top
C9286  *1U/10V_2  [C0201]  160.69 121.12 0 top
C9287  *1U/10V_2  [C0201]  155.86 108.55 90 top
C9288  *1U/10V_2  [C0201]  170.72 108.68 90 top
C9289  *1U/10V_2  [C0201]  169.96 108.68 90 top
C9290  *1U/10V_2  [C0201]  172.75 109.18 180 top
C9291  *1U/10V_2  [C0201]  156.62 108.55 90 top
C9292  *1U/10V_2  [C0201]  157.39 108.55 90 top
C9293  *1U/10V_2  [C0201]  163.35 108.68 90 top
C9294  *1U/10V_2  [C0201]  164.12 108.68 90 top
C9295  *1U/10V_2  [C0201]  164.88 108.68 90 top
C9296  *1U/10V_2  [C0201]  165.64 108.68 90 top
C9297  *1U/10V_2  [C0201]  160.05 108.68 90 top
C9298  *1U/10V_2  [C0201]  171.61 109.18 180 top
C9299  *1U/10V_2  [C0201]  160.81 108.68 90 top
C9300  *1U/10V_2  [C0201]  166.15 122.26 90 top
C9301  *10u/6.3V_4  [C0402_2]  320.15 10.25 90 top
C9302  22u/6.3V_6  [C0603]  149.77 109.31 90 top
C9303  *22u/6.3V_8  [C0805]  185.71 122.8 270 bottom
C9304  *10u/6.3V_4  [C0402_2]  267.49 33.75 270 top
C9305  0.1u/16V_4  [C0402]  258.05 69.84 225 top
C9306  22U/6.3V_6  [C0603]  241.08 73.75 0 top
C9500  10U/6.3V_4  [C0402]  261.02 9.67 270 bottom
C9501  1u/6.3V_4  [C0402]  256.06 9.67 270 bottom
C9502  0.1U/16V_2  [C0201]  188.98 21.6 0 top
C10000  *0.1u/16V_4  [C0402]  358.53 39.23 180 bottom
C10001  *0.1u/16V_4  [C0402]  358.53 40.25 180 bottom
C10002  *0.1u/16V_4  [C0402]  359.29 44.97 270 bottom
C10003  *0.1u/16V_4  [C0402]  358.27 44.97 270 bottom
C10004  *0.1u/16V_4  [C0402]  357.28 44.97 270 bottom
C10005  *0.1u/16V_4  [C0402]  356.27 44.97 270 bottom
C10006  *0.1u/16V_4  [C0402]  355.25 44.59 270 bottom
C10007  *0.1u/16V_4  [C0402]  354.24 44.59 270 bottom
C10008  *0.1u/16V_4  [C0402]  353.22 43.19 270 bottom
C10009  *0.1u/16V_4  [C0402]  352.08 43.19 270 bottom
C10010  *10u/6.3V_6  [C0603]  358.93 39.97 90 top
C10011  *0.1u/16V_4  [C0402]  360.2 39.97 90 top
C10012  *0.1u/16V_4  [C0402]  358.5 41.39 0 bottom
C10013  *10u/6.3V_6  [C0603]  358.6 42.66 0 bottom
C10014  *0.1u/16V_4  [C0402]  358.48 33.75 180 bottom
C10015  *0.1u/16V_4  [C0402]  355.07 38.59 180 bottom
C10016  *0.1u/16V_4  [C0402]  355.07 37.58 180 bottom
C10017  *0.1u/16V_4  [C0402]  358.48 34.76 180 bottom
C10018  *0.1u/16V_4  [C0402]  359.06 37.3 270 bottom
C10019  *0.1u/16V_4  [C0402]  355.07 35.45 180 bottom
C10020  *0.1u/16V_4  [C0402]  355.07 36.46 180 bottom
C10021  *0.1u/16V_4  [C0402]  354.77 30.38 270 bottom
C10022  *0.1u/16V_4  [C0402]  355.91 30.38 270 bottom
C10023  *0.1u/16V_4  [C0402]  358.05 37.3 270 bottom
C12021  *1U/6.3V_4  [C0402]  189.52 131.61 0 top
C12022  *1U/6.3V_4  [C0402]  189.53 132.63 0 top
C12023  0.1u/16V_4  [C0402]  233.33 70.78 270 top
C12024  22U/6.3V_6  [C0603]  247.05 66.16 225 top
C12025  1u/6.3V_4  [C0402]  248.32 70.86 180 top
C12026  *1U/6.3V_4  [C0402]  252.64 69.43 0 top
C12027  *1U/6.3V_4  [C0402]  253.02 68.42 0 top
C12037  0.47U/25V_4  [C0402]  50.2 60.54 270 top
C12042  3.3P/50V_4  [C0402]  333.76 26.33 180 top
C12043  0.01U/50V_4  [C0402]  362.36 62.96 90 bottom
C12044  0.1u/16V_4  [C0402]  363.38 62.96 90 bottom
C12045  0.01U/50V_4  [C0402]  363 61.18 90 bottom
C12046  0.01U/50V_4  [C0402]  364.01 61.18 90 bottom
C12047  0.1u/16V_4  [C0402]  352.08 57.11 270 bottom
C12048  0.1u/16V_4  [C0402]  350.81 57.11 270 bottom
C12049  4.7u/6.3V_4  [C0402_2]  349.54 57.11 270 bottom
C12051  0.1u/16V_4  [C0402]  358.02 55.97 270 top
C12052  0.1u/16V_4  [C0402]  357 55.97 270 top
C12054  4.7u/6.3V_4  [C0402_2]  358.05 53.68 270 bottom
C12055  0.01U/50V_4  [C0402]  356.01 53.94 180 bottom
C12056  0.1u/16V_4  [C0402]  353.35 57.11 90 bottom
C12057  0.1u/16V_4  [C0402]  355.51 58.51 180 top
C12058  0.1u/16V_4  [C0402]  355.51 59.53 180 top
C12060  0.01U/50V_4  [C0402]  355.51 60.54 0 top
C12061  0.1u/16V_4  [C0402]  356.9 61.56 90 top
C12062  0.1u/16V_4  [C0402]  357.92 61.56 90 top
C12063  0.01U/50V_4  [C0402]  358.93 61.56 270 top
C12064  1u/6.3V_4  [C0402]  363.63 55.72 180 bottom
C12065  0.1u/16V_4  [C0402]  361.09 58.51 0 top
C12066  0.01U/50V_4  [C0402]  361.09 59.53 180 top
CAS31  RHC-CP-15T13  [EMIPAD47X31-63X24-3P]  113.38 85.07 0 top
CAS33  RHC-CP-15T13  [EMIPAD47X31-63X24-3P]  130.18 85.07 0 top
CAS35  RHC-CP-15T13  [EMIPAD47X31-63X24-3P]  146.98 85.07 0 top
CAS37  RHC-CP-15T13  [EMIPAD47X31-63X24-3P]  163.78 85.07 0 top
CAS39  RHC-CP-15T13  [EMIPAD47X31-63X24-3P]  180.58 85.07 0 top
CAS40  RHC-CP-15T13  [EMIPAD47X31-63X24-3P]  185.98 79.37 90 top
CAS41  RHC-CP-15T13  [EMIPAD47X31-63X24-3P]  185.98 61.42 90 top
CAS44  RHC-CP-15T13  [EMIPAD47X31-63X24-3P]  185.98 25.42 90 top
CAS45  RHC-CP-15T13  [EMIPAD47X31-63X24-3P]  185.98 9.4 90 top
CAS46  RHC-CP-15T13  [EMIPAD47X31-63X24-3P]  180.58 3.73 0 top
CAS48  RHC-CP-15T13  [EMIPAD47X31-63X24-3P]  163.78 3.73 0 top
CAS50  RHC-CP-15T13  [EMIPAD47X31-63X24-3P]  146.98 3.73 0 top
CAS51  RHC-CP-15T13  [EMIPAD47X31-63X24-3P]  107.98 79.37 90 top
CAS59  RHC-CP-15T13  [EMIPAD47X31-63X24-3P]  113.38 3.73 0 top
CAS65  RHC-CP-15T13  [EMIPAD47X31-63X24-3P]  130.18 3.73 0 top
CAS66  RHC-CP-15T13  [EMIPAD47X31-63X24-3P]  107.98 9.4 90 top
CAS68  RHC-CP-15T13  [EMIPAD47X31-63X24-3P]  107.98 25.42 90 top
CAS69  RHC-CP-15T13  [EMIPAD47X31-63X24-3P]  107.98 61.42 90 top
CON400  *Samtec BSH-030-01  [BSH-030-01-L-D-A-TR-60P-RUV]  83.98 65.75 0 bottom
CON401  *APS CONN.  [88511-180N-18P-L]  253.65 37.94 180 bottom
CON3000  eDP conn.  [LVDS-GS12407-10112-7H-40P-R]  55.68 55.9 0 bottom
CON3001  TS_CONN  [WTB-50450-0127C-001-12P-L]  30.59 59.8 0 bottom
CON3002  ALS_CONN  [WTB-50450-0107C-001-10P-L]  17.57 59.8 0 bottom
CON3200  HDMI CONN  [HDMI-HMRFD-AK520C-19P]  366.64 96.15 90 top
CON3601  2SJ3088-027211F  [AUDIO-2SJ3088-027211F-6P]  361.8 7.97 90 top
CON3602  INT SPEAKER CONN  [50207-00471-001-4P-L-SMT]  212.76 156 0 bottom
CON4000  RJ45_CONN  [RJ45-2RJ1748-002111F-12P]  9.55 125.19 270 top
CON4200  MICRO SIM_CONN  [SIMCARD-159-1000302600-10P-L]  305.69 0.93 180 bottom
CON4201  WWAN_NGFF CONN  [NGFF-NFSB0-S6715-TP40-75P-KB]  340 13.9 0 bottom
CON5000  C166KS_12231-L  [HDD-C166PK-12234-L-22P-R]  49.6 40.98 0 top
CON5100  SSD_NGFF_CONN_75P  [NGFF-NFSM0-S6710-TP58-75P-KM]  317.78 36.4 90 bottom
CON5101  SSD_NGFF_CONN_75P  [NGFF-NFSM0-S6710-TP58-75P-KM]  318.18 13.4 90 bottom
CON6000  Power switch conn.  [51619-00801-V03-8P-L]  34.48 147.35 0 bottom
CON6300  FAN Conn.  [50273-0040N-V09-4P-L]  31.39 99.62 285 bottom
CON6301  FAN Conn.  [50273-0040N-V09-4P-L]  332.65 94.6 68.9 bottom
CON6351  CLICK PAD_CONN  [FPC-51625-0120B-V01-12P-L]  105.73 4.04 180 bottom
CON6352  STICK POINT_CONN  [51653-00401-V01-4P-L]  79.83 56.1 0 top
CON6800  KB CONN  [51697-0420M-001-42P-L]  230.68 48.24 270 top
CON6801  KB_LIGHT_CONN  [51619-00801-V03-8P-L]  194.08 51.75 180 top
CON7000  USB3.0 CONN  [UB3-TAR24-9R6396-9P]  5.65 107.32 270 top
CON7001  USB3.0 CONN  [UB3-TAR24-9R6396-9P]  364.31 75.2 90 top
CON7002  USB3.0 CONN  [UB3-TAR24-9R6396-9P]  5.65 88.82 270 top
CON7100  TYPE_C_CONN  [UB31-UT1211C-1340Q-7H-24P]  362.56 131.96 90 top
CON7101  TYPE_C_CONN  [UB31-UT1211C-1340Q-7H-24P]  362.56 115.32 90 top
CON7200  FPR conn.  [51619-00801-V03-8P-L]  291.45 5.9 180 bottom
CON7300  SMART CONN  [50524-01001-001-10P-L]  277 3.35 180 bottom
CON7301  5-531706004000-6  [SDCARD-5-531706004000-6-19P]  19.77 61.64 270 top
CON9000  RTC_CONN  [RTC-53011-0020K-V09-2P]  345.63 49 0 top
CON9500  NFC CONN  [50506-01501-V01-15P-L]  258.43 4.75 180 bottom
CON10002  DREAM COLOR_CONN  [FPC-51619-0060B-001-6P-L]  245.58 5.35 180 bottom
D2003  MEK500V-40  [DSM]  222.66 90.48 180 top
D2004  RB500V-40  [DSM]  217.23 78.75 180 top
D2008  BAT54AW-L  [SOT323_213-2_1-1_3-3P]  198.15 88.83 90 bottom
D3001  *MEK500V-40  [DSM]  35.12 47.28 90 bottom
D3002  *SDM20U30-7  [D-1_2X0_8-0_7H]  54.74 46.14 180 top
D3600  *BAT54AW-L  [SOT323_213-2_1-1_3-3P]  333.15 16.85 180 top
D4200  SDM20U30-7  [D-1_2X0_8-0_7H]  334.46 20.76 270 bottom
D5100  *1SS355  [DSM]  317.76 16.63 270 top
D5101  *1SS355  [DSM]  319.56 6.65 0 top
D6000  *SDM20U30-7  [D-1_2X0_8-0_7H]  277.93 31.51 90 top
D6001  SDM20U30-7  [D-1_2X0_8-0_7H]  277.93 31.51 270 bottom
D6800  BAW56DW  [SOT363-2_1-65-6P]  236.63 46.57 180 bottom
D6801  BAW56DW  [SOT363-2_1-65-6P]  236.63 41.44 180 bottom
D6802  BAW56DW  [SOT363-2_1-65-6P]  236.63 43.91 180 bottom
D6803  BAW56DW  [SOT363-2_1-65-6P]  237.37 49.11 180 bottom
D7100  D5V0X1B2LP-7B  [D-1X0_6-D24V0L1B2LPS]  358.93 110.45 180 top
D7101  P4SMAFJ20A  [D-3_8X2_5]  354.9 127.75 180 top
D7102  D5V0X1B2LP-7B  [D-1X0_6-D24V0L1B2LPS]  359.32 125.44 270 top
D7103  D5V0X1B2LP-7B  [D-1X0_6-D24V0L1B2LPS]  359.32 125.57 90 bottom
D7104  PESD5V0H1BSF  [D-0_6X0_3-0_32H-SMT]  358.81 132.81 270 bottom
D7105  PESD5V0H1BSF  [D-0_6X0_3-0_32H-SMT]  358.81 131.41 90 bottom
D7106  PESD5V0H1BSF  [D-0_6X0_3-0_32H-SMT]  358.81 135.6 270 bottom
D7107  PESD5V0H1BSF  [D-0_6X0_3-0_32H-SMT]  358.81 132.68 270 top
D7108  PESD5V0H1BSF  [D-0_6X0_3-0_32H-SMT]  358.81 134.2 90 bottom
D7109  PESD5V0H1BSF  [D-0_6X0_3-0_32H-SMT]  358.81 131.28 90 top
D7110  PESD5V0H1BSF  [D-0_6X0_3-0_32H-SMT]  357.66 135.22 270 top
D7111  PESD5V0H1BSF  [D-0_6X0_3-0_32H-SMT]  358.93 130.01 270 bottom
D7112  PESD5V0H1BSF  [D-0_6X0_3-0_32H-SMT]  357.66 133.82 90 top
D7113  PESD5V0H1BSF  [D-0_6X0_3-0_32H-SMT]  358.93 128.61 90 bottom
D7114  PESD5V0H1BSF  [D-0_6X0_3-0_32H-SMT]  359.77 126.99 0 bottom
D7115  PESD5V0H1BSF  [D-0_6X0_3-0_32H-SMT]  359.32 130.01 270 top
D7116  PESD5V0H1BSF  [D-0_6X0_3-0_32H-SMT]  359.82 133.31 270 bottom
D7117  PESD5V0H1BSF  [D-0_6X0_3-0_32H-SMT]  359.32 128.61 90 top
D7118  P4SMAFJ20A  [D-3_8X2_5]  353.52 122.54 180 top
D7119  D5V0X1B2LP-7B  [D-1X0_6-D24V0L1B2LPS]  358.86 110.4 270 bottom
D7120  PESD5V0H1BSF  [D-0_6X0_3-0_32H-SMT]  358.81 116.04 270 bottom
D7121  PESD5V0H1BSF  [D-0_6X0_3-0_32H-SMT]  358.81 114.64 90 bottom
D7122  PESD5V0H1BSF  [D-0_6X0_3-0_32H-SMT]  359.19 118.33 180 bottom
D7123  PESD5V0H1BSF  [D-0_6X0_3-0_32H-SMT]  358.81 115.91 270 top
D7124  PESD5V0H1BSF  [D-0_6X0_3-0_32H-SMT]  359.19 117.31 180 bottom
D7125  PESD5V0H1BSF  [D-0_6X0_3-0_32H-SMT]  358.81 114.52 90 top
D7126  PESD5V0H1BSF  [D-0_6X0_3-0_32H-SMT]  358.71 118.58 270 top
D7127  PESD5V0H1BSF  [D-0_6X0_3-0_32H-SMT]  358.81 113.25 270 bottom
D7128  PESD5V0H1BSF  [D-0_6X0_3-0_32H-SMT]  358.71 117.21 90 top
D7129  PESD5V0H1BSF  [D-0_6X0_3-0_32H-SMT]  358.81 111.95 90 bottom
D7130  PESD5V0H1BSF  [D-0_6X0_3-0_32H-SMT]  360.71 110.45 0 bottom
D7131  PESD5V0H1BSF  [D-0_6X0_3-0_32H-SMT]  358.78 113.12 270 top
D7132  PESD5V0H1BSF  [D-0_6X0_3-0_32H-SMT]  359.82 116.17 270 bottom
D7133  PESD5V0H1BSF  [D-0_6X0_3-0_32H-SMT]  358.78 111.72 90 top
D7170  *SDM20U30-7  [D-1_2X0_8-0_7H]  358.68 120.28 270 bottom
D7171  *SDM20U30-7  [D-1_2X0_8-0_7H]  359.39 123.2 90 bottom
D7300  *LCP0G050M0R2R_0.2p  [R0402]  36.38 69.31 270 top
D7301  *LCP0G050M0R2R_0.2p  [R0402]  36.13 71.21 90 top
D7302  *LCP0G050M0R2R_0.2p  [R0402]  33.74 52.97 270 bottom
D7303  *LCP0G050M0R2R_0.2p  [R0402]  36.74 52.8 0 top
D7304  *LCP0G050M0R2R_0.2p  [R0402]  36.61 58.89 0 top
D7305  *LCP0G050M0R2R_0.2p  [R0402]  36.23 64.86 270 top
D7306  *LCP0G050M0R2R_0.2p  [R0402]  36.58 74.31 0 top
D7307  *LCP0G050M0R2R_0.2p  [R0402]  38.54 66.05 0 bottom
D8000  MEK500V-40  [DSM]  351.14 102.28 270 top
D9000  BAT54CW  [SOT323_213-2_1-1_3-2N7002W]  322.15 9.67 0 top
D9001  BAT54SW-L  [SOT323_213-2_1-1_3-2N7002W]  200.06 25.46 270 bottom
D9003  MEK500V-40  [DSM]  46.9 62.5 90 top
D9004  *MEK500V-40  [DSM]  360.63 44.54 90 top
EC3600  *10p/50V_4  [C0402]  338.36 16.46 90 top
EC3601  0.1u/16V_4  [C0402]  353.42 8.96 0 bottom
EC3602  0.1u/16V_4  [C0402]  353.42 8.96 0 top
EC3603  *10p/50V_4  [C0402]  335.31 14.73 270 top
EC3604  *10p/50V_4  [C0402]  339.93 18.06 0 top
EC3605  *10p/50V_4  [C0402]  339.76 16.28 90 top
EC5101  10u/6.3V_6  [C0603]  311.18 21.17 0 bottom
EC5102  10u/6.3V_6  [C0603]  311.51 44.59 270 bottom
EC5103  22u/25V_8  [C0805]  69.07 49.77 0 bottom
EC5104  56p/50V_4  [C0402]  66.58 50.89 90 bottom
EC9000  10U/6.3V_4  [C0402]  48.67 50.76 270 top
EC9001  47p/50V_4  [C0402]  49.69 50.76 90 top
EC9002  10U/6.3V_4  [C0402]  25.05 53.05 0 bottom
EC9003  56p/50V_4  [C0402]  25.05 52.03 0 bottom
EC9004  10u/25V_6  [C0603]  237.8 155.11 180 top
EC9005  10u/25V_6  [C0603]  126.14 131.23 180 bottom
EC9006  68P/50V_4  [C0402]  223.93 157.82 270 top
EC9007  68P/50V_4  [C0402]  227.87 156.94 270 top
EC9008  10u/25V_6  [C0603]  207.32 44.26 270 bottom
EC9009  10u/25V_6  [C0603]  205.87 44.26 270 bottom
EC9010  10u/25V_6  [C0603]  208.77 44.26 270 bottom
EC9011  10U/6.3V_4  [C0402]  190.57 46.77 0 bottom
EC9012  10u/25V_6  [C0603]  213.57 26.38 90 bottom
EC9013  10U/6.3V_4  [C0402]  170.34 93.82 90 bottom
EC9014  10u/25V_6  [C0603]  216.47 30.19 0 bottom
EC9015  10U/6.3V_4  [C0402]  308.96 35.54 0 bottom
EC9016  5.6p/50V_4  [C0402]  309.03 30.94 0 bottom
EC9017  5.6p/50V_4  [C0402]  309.02 29.86 0 bottom
EC9018  10U/6.3V_4  [C0402]  308.97 36.62 0 bottom
EC9019  10U/6.3V_4  [C0402]  38.51 62.32 180 bottom
EC9020  27P/50V_4  [C0402]  38.51 63.34 0 bottom
EC9021  6.8P/50V_4  [C0402]  94.01 50.38 180 top
EC9022  10U/6.3V_4  [C0402]  94.01 51.4 180 top
EC9023  4.7u/6.3V_4  [C0402]  18.32 97.5 270 bottom
EC9024  47p/50V_4  [C0402]  40.37 61.66 180 bottom
EC9025  10u/25V_6  [C0603]  102.22 81.09 180 top
EC9026  10u/25V_6  [C0603]  116.19 112.03 90 top
EC9027  10u/25V_6  [C0603]  117.68 112.03 90 top
EC9028  10u/25V_6  [C0603]  102.55 75.76 180 top
EC9029  10U/6.3V_4  [C0402]  47.63 50.41 270 bottom
EC9030  10U/6.3V_4  [C0402]  190.94 133.16 90 top
EC9031  10u/25V_6  [C0603]  120.73 124.96 90 top
EC9032  10U/6.3V_4  [C0402]  57.92 68.9 270 bottom
EC9033  68P/50V_4  [C0402]  287.66 14.92 90 top
EC9034  10U/6.3V_4  [C0402]  65.87 47.39 270 bottom
EC9036  68P/50V_4  [C0402]  38.69 47.21 90 bottom
EC9037  10U/6.3V_4  [C0402]  40.8 50.03 0 bottom
EC9038  68P/50V_4  [C0402]  40.8 51.07 180 bottom
EC9039  22u/6.3V_6  [C0603]  344.56 23.13 0 bottom
EC9040  4.7u/6.3V_4  [C0402]  328.58 22.04 0 bottom
EC9041  10U/6.3V_4  [C0402]  84.87 72.53 270 top
EC9042  68P/50V_4  [C0402]  85.93 72.79 90 top
EC9043  22u/6.3V_6  [C0603]  256.95 47.67 225 bottom
EC9044  4.7u/6.3V_4  [C0402]  86.01 52.31 0 bottom
EC9045  4.7u/6.3V_4  [C0402]  120.76 103.39 0 bottom
EC9046  56p/50V_4  [C0402]  124.24 97.2 180 bottom
EC9047  6.8P/50V_4  [C0402]  37.37 69.31 90 top
EC9048  6.8P/50V_4  [C0402]  37.12 71.21 270 top
EC9049  6.8P/50V_4  [C0402]  34.7 52.97 90 bottom
EC9050  6.8P/50V_4  [C0402]  36.74 51.4 180 top
EC9051  6.8P/50V_4  [C0402]  36.21 66.64 270 top
ESD4200  AZC099-04S  [SOT236-2_9-95-6P]  308.64 10.12 180 top
ESD7200  AZC099-04S  [SOT236-2_9-95-6P]  292.77 11.77 0 bottom
F3000  FUSE1.5A 24V_POLY  [F4_55X3_24-5_23-1_8H]  72.04 48.35 0 top
F7200  FUSE0.65A 6V_POLY  [R0603]  289.08 11.52 0 top
H1  *H-TC217BC256I118D118P2  [H-TC217BC256I118D118P2]  136.38 159 180 bottom
H2  *H-TC217BC256I118D118P2  [H-TC217BC256I118D118P2]  233.58 159 180 bottom
H3  *H-C256I118D118P2  [H-C256I118D118P2]  19.25 81.79 180 bottom
H4  *H-C276I118D118P2  [H-C276I118D118P2]  50.19 71.86 0 top
H5  hg-tc216ic128bc157d61p2  [HG-TC216IC128BC157D61P2]  72.18 55.9 180 bottom
H6  hg-tc216ic128bc157d61p2  [HG-TC216IC128BC157D61P2]  39.18 55.9 180 bottom
H7  *H-C256I118D118P2  [H-C256I118D118P2]  100.12 11.9 180 bottom
H8  *H-C394I118D118P2  [H-C394I118D118P2]  111.76 105.73 180 bottom
H9  *H-TC217BC256I118D118P2  [H-TC217BC256I118D118P2]  4.38 136.7 180 bottom
H10  *H-TC217BC256I118D118P2  [H-TC217BC256I118D118P2]  26.13 42.47 180 bottom
H11  *H-TC236BC256I146D146P2  [H-TC236BC256I146D146P2]  183.58 135.7 180 bottom
H12  *H-TC236BC256I146D146P2  [H-TC236BC256I146D146P2]  134.58 92 180 bottom
H13  *H-TC236BC256I146D146P2  [H-TC236BC256I146D146P2]  244.78 92 180 bottom
H14  *H-TC236BC256I146D146P2  [H-TC236BC256I146D146P2]  134.58 135.7 180 bottom
H15  *H-TC236BC256I146D146P2  [H-TC236BC256I146D146P2]  244.78 135.7 180 bottom
H16  *H-TC236BC256I146D146P2  [H-TC236BC256I146D146P2]  183.58 92 180 bottom
H17  *H-C394I118D118P2  [H-C394I118D118P2]  341.61 82 180 bottom
H18  *H-C256I118D118P2  [H-C256I118D118P2]  7.88 41 180 bottom
H19  *H-C256I118D118P2  [H-C256I118D118P2]  362.98 19.6 180 bottom
H20  -  [H-TC217IC102BC256D102P2]  239.53 36.4 180 bottom
H21  *H-C394I118D118P2  [H-C394I118D118P2]  257.98 95.7 180 bottom
H22  *H-TO276X236BIO157X118D157X118PT  [H-TO276X236BIO157X118D157X118PT]  330.72 149 0 top
H23  *H-XW2A-B3  [H-XW2A-B3]  364.78 107 0 top
H24  *H-XW2A-B1  [H-XW2A-B1]  350.98 149.3 0 top
H25  *H-XW2A-B2  [H-XW2A-B2]  365.15 123.7 0 top
H26  *H-TIO256X236BO138X118D138X118PT  [H-TIO256X236BO138X118D138X118PT]  361.23 25.6 180 top
H27  *H-C256I118D118P2  [H-C256I118D118P2]  92.53 56.67 180 bottom
H28  -  [H-TC236BC177I138D138P2]  340 54.15 180 bottom
H29  -  [H-TC217IC102BC256D102P2]  239.93 13.4 180 bottom
H30  *H-TC256BC217I118D118P2  [H-TC256BC217I118D118P2]  201.59 4.7 180 bottom
H31  *H-C256I118D118P2  [H-C256I118D118P2]  284.78 59.17 180 bottom
H32  *H-TC217BC256I118D118P2  [H-TC217BC256I118D118P2]  18.25 117.36 180 bottom
H33  *H-C256I118D118P2  [H-C256I118D118P2]  222.05 74.93 180 bottom
H34  *H-C118D118N  [H-C118D118N]  4.21 78.68 180 bottom
H35  *SPAD-C236NP  [SPAD-C236NP]  201.34 38.42 0 top
J9000  *SOLDERJUMPER-2  [SOLDERJUMPER-2]  304.45 15.81 180 top
JCN9000  *EC debug conn.  [LVDS-LVD-A30SFYG-30P-R]  267.49 13.93 180 bottom
JDIM1000  DDR4-DIMM0_H=4_STD  [DDR4-D4AS0-26010-1P40-STD-SMT]  146.98 52.57 0 top
JDIM1001  DDR3-DIMM0_H=4_RVS  [DDR4-D4AR0-26001-1P40-RVS-SMT]  146.98 52.57 180 bottom
JDIM1002  DDR4-DIMM0_H=4_STD  [DDR4-ADDR0207-P035A-STD-260P]  146.98 36.23 0 bottom
JDIM1003  DDR3-DIMM0_H=4_RVS  [DDR4-D4AR0-26001-1P40-RVS-SMT]  146.98 36.23 180 top
L2001  HCB1005KF-330T30  [R0402]  195.23 132.3 90 top
L2010  HCB1005KF-330T30  [R0402]  193.81 131.61 0 top
L3003  SBY100505T-601Y-N  [R0402]  342.7 20.7 0 top
L3004  MCM2012B900GBE  [CHOKE-WCM2012-4P]  49.18 47.08 90 bottom
L3005  SBY100505T-601Y-N  [R0402]  45.7 59.78 90 bottom
L3604  *0_6/S  [S0603]  349.54 27.73 270 top
L3605  FCM1005KF-301T03  [R0402]  356.24 10.43 180 top
L3606  FCM1005KF-301T03  [R0402]  353.47 3.39 270 top
L3607  PIME031B-1R0MS  [L3_1X3_1]  226.35 157.16 90 bottom
L3608  PIME031B-1R0MS  [L3_1X3_1]  199.68 158.43 180 bottom
L3609  *0_6/S  [S0603]  216.82 155.25 270 top
